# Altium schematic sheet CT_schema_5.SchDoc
size 469 x 363 mm
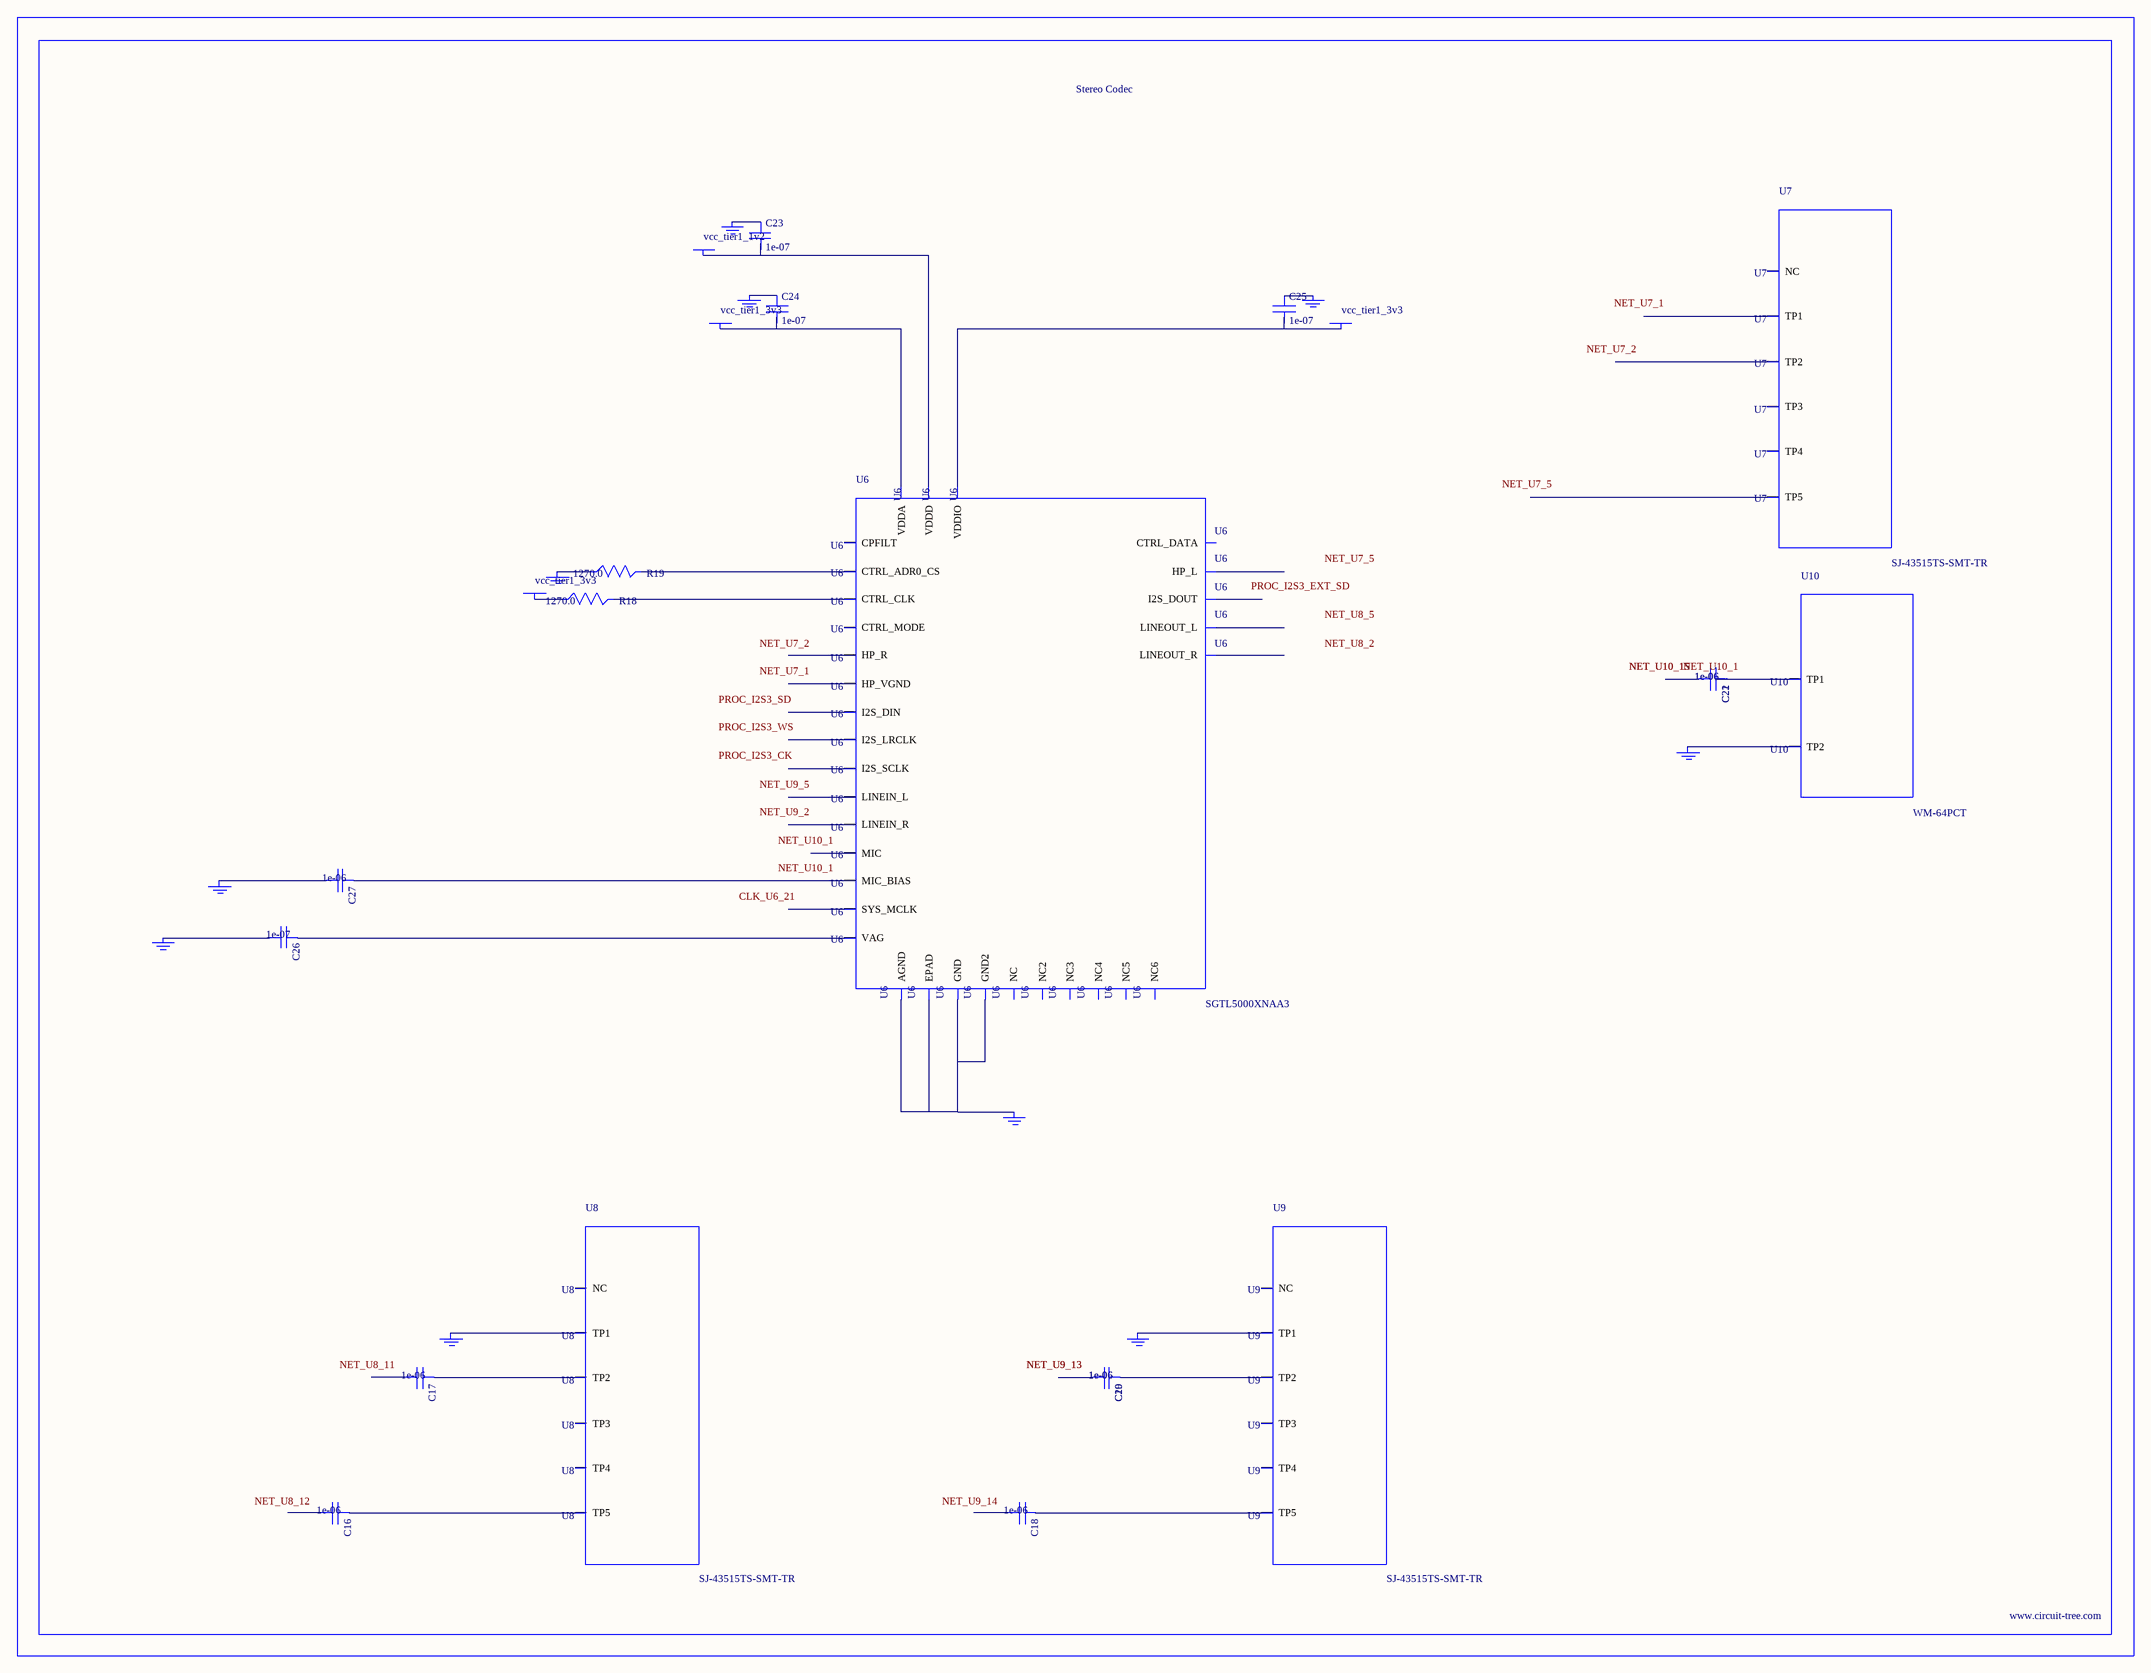
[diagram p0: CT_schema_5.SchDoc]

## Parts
BORDER4  (no value)
C16  1e-06  [C0603]
C17  1e-06  [C0603]
C18  1e-06  [C0603]
C19  1e-06  [C0603]
C20  1e-06  [C0603]
C21  1e-06  [C0603]
C22  1e-06  [C0603]
C23  1e-07  [C0402]
C24  1e-07  [C0402]
C25  1e-07  [C0402]
C26  1e-07  [C0402]
C27  1e-06  [C0603]
GND_INSTANCE_4_0  (no value)
GND_INSTANCE_4_1  (no value)
GND_INSTANCE_4_2  (no value)
GND_INSTANCE_4_3  (no value)
GND_INSTANCE_4_4  (no value)
GND_INSTANCE_4_5  (no value)
GND_INSTANCE_4_6  (no value)
GND_INSTANCE_4_7  (no value)
GND_INSTANCE_4_8  (no value)
GND_INSTANCE_4_9  (no value)
GND_INSTANCE_4_10  (no value)
POWER_INSTANCE_4_0  vcc_tier1_3v3
POWER_INSTANCE_4_1  vcc_tier1_3v3
POWER_INSTANCE_4_2  vcc_tier1_3v3
POWER_INSTANCE_4_3  vcc_tier1_1v2
R18  1270.0  [R0603]
R19  1270.0  [R0603]
U6  SGTL5000XNAA3  [QFN-32]
U7  SJ-43515TS-SMT-TR  [SJ-43515TS-SMT-TR]
U8  SJ-43515TS-SMT-TR  [SJ-43515TS-SMT-TR]
U9  SJ-43515TS-SMT-TR  [SJ-43515TS-SMT-TR]
U10  WM-64PCT  [WM-64PC]

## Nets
NetC16_1: C16.1 U8.5(TP5)
NetC17_1: C17.1 U8.2(TP2)
NetC18_1: C18.1 U9.5(TP5)
NetC19_1: C19.1 C20.1 U9.2(TP2)
NetC19_2: C19.2 C20.2
NetC21_1: C21.1 C22.1 U10.1(TP1)
NetC21_2: C21.2 C22.2
NetC23_1: C23.1 GND_INSTANCE_4_5.0(GND)
NetC23_2: C23.2 POWER_INSTANCE_4_3.0(PWR) U6.30(VDDD)
NetC24_1: C24.1 GND_INSTANCE_4_1.0(GND)
NetC24_2: C24.2 POWER_INSTANCE_4_0.0(PWR) U6.5(VDDA)
NetC25_1: C25.1 GND_INSTANCE_4_4.0(GND)
NetC25_2: C25.2 POWER_INSTANCE_4_1.0(PWR) U6.20(VDDIO)
NetC26_1: C26.1 U6.10(VAG)
NetC26_2: C26.2 GND_INSTANCE_4_2.0(GND)
NetC27_1: C27.1 U6.16(MIC_BIAS)
NetC27_2: C27.2 GND_INSTANCE_4_3.0(GND)
NetGND_INSTANCE_4_0_0: GND_INSTANCE_4_0.0(GND) U6.1(GND) U6.3(GND2) U6.7(AGND) U6.EXP(EPAD)
NetGND_INSTANCE_4_6_0: GND_INSTANCE_4_6.0(GND) R19.1
NetGND_INSTANCE_4_7_0: GND_INSTANCE_4_7.0(GND) U8.1(TP1)
NetGND_INSTANCE_4_8_0: GND_INSTANCE_4_8.0(GND) GND_INSTANCE_4_9.0(GND) U9.1(TP1)
NetGND_INSTANCE_4_10_0: GND_INSTANCE_4_10.0(GND) U10.2(TP2)
NetPOWER_INSTANCE_4_2_0: POWER_INSTANCE_4_2.0(PWR) R18.1
NetR18_2: R18.2 U6.29(CTRL_CLK)
NetR19_2: R19.2 U6.31(CTRL_ADR0_CS)

Not connected (* = marked no-connect by the designer): C16 2; C17 2; C18 2; U6 2(HP_R) 4(HP_VGND) 6(HP_L) 8(NC) 9(NC2) 11(LINEOUT_R) 12(LINEOUT_L) 13(LINEIN_R) 14(LINEIN_L) 15(MIC) 17(NC3) 18(CPFILT) 19(NC4) 21(SYS_MCLK) 22(NC5) 23(I2S_LRCLK) 24(I2S_SCLK) 25(I2S_DOUT) 26(I2S_DIN) 27(CTRL_DATA) 28(NC6) 32(CTRL_MODE); U7 1(TP1) 2(TP2) 3(TP3) 4(TP4) 5(TP5) 6(NC); U8 3(TP3) 4(TP4) 6(NC); U9 3(TP3) 4(TP4) 6(NC)

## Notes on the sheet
- Labels drawn without touching a wire or pin: CLK_U6_21, NET_U7_1, NET_U7_2, NET_U7_5, NET_U8_2, NET_U8_5, NET_U8_11, NET_U8_12, NET_U9_2, NET_U9_5, NET_U9_14, NET_U10_1, PROC_I2S3_CK, PROC_I2S3_EXT_SD, PROC_I2S3_SD, PROC_I2S3_WS

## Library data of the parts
BORDER4 = BORDER_PAGE4
C16-C22 C27 = C0603C105K3RACTU
C23-C26 = C0402C104K3RACTU
GND_INSTANCE_4_0-GND_INSTANCE_4_10 = GND
POWER_INSTANCE_4_0-POWER_INSTANCE_4_3 = PWR
R18 R19 = RC0603FR-071K27L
